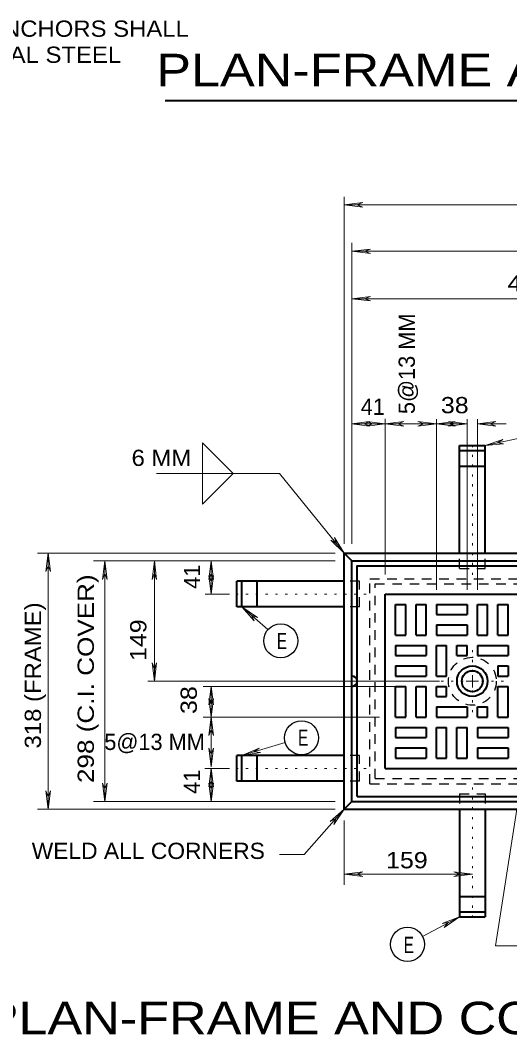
# Model space of a CAD drawing. Extents: x 312583 to 312854, y 144419 to 144597.
# Drawn here: x 312630.54 to 312653.44, y 144489.61 to 144537.06 of the extents above; entities that cross this region are included whole.
import ezdxf
from ezdxf.enums import TextEntityAlignment as Align

# ---------------------------------------------------------------- set-up
doc = ezdxf.new("R2010")
doc.units = 0
doc.header["$LTSCALE"] = 0.3
doc.linetypes.add('DOTTED', pattern=[1.5, 0.3, -1.2])
doc.linetypes.add('SHORT_DASHED', pattern=[2.7, 1.5, -1.2])
doc.layers.add('1', color=7, linetype='Continuous', lineweight=13)

msp = doc.modelspace()

# ---------------------------------------------------------------- linework, layer by layer
at = {"layer": '1', "lineweight": 40}
for p, q in [((312637.3201, 144533.3146), (312710.5195, 144533.3146)), ((312651.0931, 144517.1686), (312652.2891, 144517.1686)), ((312651.0931, 144512.1393), (312651.0931, 144517.1686)), ((312652.2891, 144512.1393), (312652.2891, 144517.1686)), ((312651.0931, 144516.931), (312652.2891, 144516.931)), ((312651.0931, 144516.2103), (312652.2891, 144516.2103)), ((312645.6958, 144500.1563), (312645.6958, 144512.1393)), ((312645.6958, 144512.1393), (312682.5955, 144512.1393)), ((312645.6958, 144512.1393), (312646.0561, 144511.779)), ((312646.0561, 144500.5166), (312646.0561, 144511.779)), ((312646.0561, 144511.779), (312682.2351, 144511.779)), ((312640.6665, 144509.6246), (312640.6665, 144510.8206)), ((312645.6958, 144510.8206), (312640.6665, 144510.8206)), ((312640.9041, 144509.6246), (312640.9041, 144510.8206)), ((312641.6248, 144509.6246), (312641.6248, 144510.8206)), ((312647.6125, 144502.073), (312647.6125, 144510.2226)), ((312647.6125, 144510.2226), (312680.6788, 144510.2226)), ((312645.6958, 144509.6246), (312640.6665, 144509.6246)), ((312648.0955, 144508.306), (312648.0955, 144509.7396)), ((312648.0955, 144509.7396), (312648.5708, 144509.7396)), ((312648.5708, 144508.306), (312648.5708, 144509.7396)), ((312649.0538, 144508.306), (312649.0538, 144509.7396)), ((312649.0538, 144509.7396), (312649.5291, 144509.7396)), ((312649.5291, 144508.306), (312649.5291, 144509.7396)), ((312650.0121, 144509.7396), (312651.4458, 144509.7396)), ((312650.0121, 144509.7396), (312650.0121, 144509.2643)), ((312651.4458, 144509.7396), (312651.4458, 144509.2643)), ((312651.9288, 144508.306), (312651.9288, 144509.7396)), ((312651.9288, 144509.7396), (312652.4041, 144509.7396)), ((312652.4041, 144508.306), (312652.4041, 144509.7396)), ((312652.8871, 144508.306), (312652.8871, 144509.7396)), ((312652.8871, 144509.7396), (312653.3625, 144509.7396)), ((312653.3625, 144508.306), (312653.3625, 144509.7396)), ((312650.0121, 144509.2643), (312651.4458, 144509.2643)), ((312650.0121, 144508.7813), (312651.4458, 144508.7813)), ((312650.0121, 144508.7813), (312650.0121, 144508.306)), ((312651.4458, 144508.7813), (312651.4458, 144508.306)), ((312648.0955, 144508.306), (312648.5708, 144508.306)), ((312649.0538, 144508.306), (312649.5291, 144508.306)), ((312650.0121, 144508.306), (312651.4458, 144508.306)), ((312651.9288, 144508.306), (312652.4041, 144508.306)), ((312652.8871, 144508.306), (312653.3625, 144508.306)), ((312648.0955, 144507.823), (312649.5291, 144507.823)), ((312648.0955, 144507.823), (312648.0955, 144507.3476)), ((312649.5291, 144507.823), (312649.5291, 144507.3476)), ((312650.0121, 144506.3893), (312650.0121, 144507.823)), ((312650.0121, 144507.823), (312650.4875, 144507.823)), ((312650.4875, 144506.3893), (312650.4875, 144507.823)), ((312650.9705, 144507.3476), (312650.9705, 144507.823)), ((312650.9705, 144507.823), (312651.4458, 144507.823)), ((312651.4458, 144507.3476), (312651.4458, 144507.823)), ((312651.9288, 144507.823), (312653.3625, 144507.823)), ((312651.9288, 144507.823), (312651.9288, 144507.3476)), ((312653.3625, 144507.823), (312653.3625, 144507.3476)), ((312648.0955, 144507.3476), (312649.5291, 144507.3476)), ((312650.9705, 144507.3476), (312651.4458, 144507.3476)), ((312651.9288, 144507.3476), (312653.3625, 144507.3476)), ((312648.0955, 144506.8646), (312649.5291, 144506.8646)), ((312648.0955, 144506.8646), (312648.0955, 144506.3893)), ((312649.5291, 144506.8646), (312649.5291, 144506.3893)), ((312652.8871, 144506.8646), (312653.3625, 144506.8646)), ((312652.8871, 144506.8646), (312652.8871, 144506.3893)), ((312653.3625, 144506.8646), (312653.3625, 144506.3893)), ((312648.0955, 144506.3893), (312649.5291, 144506.3893)), ((312650.0121, 144506.3893), (312650.4875, 144506.3893)), ((312652.8871, 144506.3893), (312653.3625, 144506.3893)), ((312648.0955, 144504.4726), (312648.0955, 144505.9063)), ((312648.0955, 144505.9063), (312648.5708, 144505.9063)), ((312648.5708, 144504.4726), (312648.5708, 144505.9063)), ((312649.0538, 144504.4726), (312649.0538, 144505.9063)), ((312649.0538, 144505.9063), (312649.5291, 144505.9063)), ((312649.5291, 144504.4726), (312649.5291, 144505.9063)), ((312650.0121, 144505.431), (312650.0121, 144505.9063)), ((312650.0121, 144505.9063), (312650.4875, 144505.9063)), ((312650.4875, 144505.431), (312650.4875, 144505.9063)), ((312652.8871, 144504.4726), (312652.8871, 144505.9063)), ((312652.8871, 144505.9063), (312653.3625, 144505.9063)), ((312653.3625, 144504.4726), (312653.3625, 144505.9063)), ((312650.0121, 144505.431), (312650.4875, 144505.431)), ((312650.0121, 144504.948), (312651.4458, 144504.948)), ((312650.0121, 144504.948), (312650.0121, 144504.4726)), ((312651.4458, 144504.948), (312651.4458, 144504.4726)), ((312651.9288, 144504.4726), (312651.9288, 144504.948)), ((312651.9288, 144504.948), (312652.4041, 144504.948)), ((312652.4041, 144504.4726), (312652.4041, 144504.948)), ((312648.0955, 144504.4726), (312648.5708, 144504.4726)), ((312649.0538, 144504.4726), (312649.5291, 144504.4726)), ((312650.0121, 144504.4726), (312651.4458, 144504.4726)), ((312651.9288, 144504.4726), (312652.4041, 144504.4726)), ((312652.8871, 144504.4726), (312653.3625, 144504.4726)), ((312648.0955, 144503.9896), (312649.5291, 144503.9896)), ((312648.0955, 144503.9896), (312648.0955, 144503.5143)), ((312649.5291, 144503.9896), (312649.5291, 144503.5143)), ((312650.0121, 144502.556), (312650.0121, 144503.9896)), ((312650.0121, 144503.9896), (312650.4875, 144503.9896)), ((312650.4875, 144502.556), (312650.4875, 144503.9896)), ((312650.9705, 144502.556), (312650.9705, 144503.9896)), ((312650.9705, 144503.9896), (312651.4458, 144503.9896)), ((312651.4458, 144502.556), (312651.4458, 144503.9896)), ((312651.9288, 144503.9896), (312653.3625, 144503.9896)), ((312651.9288, 144503.9896), (312651.9288, 144503.5143)), ((312653.3625, 144503.9896), (312653.3625, 144503.5143)), ((312648.0955, 144503.5143), (312649.5291, 144503.5143)), ((312651.9288, 144503.5143), (312653.3625, 144503.5143)), ((312648.0955, 144503.0313), (312649.5291, 144503.0313)), ((312648.0955, 144503.0313), (312648.0955, 144502.556)), ((312649.5291, 144503.0313), (312649.5291, 144502.556)), ((312651.9288, 144503.0313), (312653.3625, 144503.0313)), ((312651.9288, 144503.0313), (312651.9288, 144502.556)), ((312653.3625, 144503.0313), (312653.3625, 144502.556)), ((312640.6665, 144501.475), (312640.6665, 144502.671)), ((312645.6958, 144502.671), (312640.6665, 144502.671)), ((312640.9041, 144501.475), (312640.9041, 144502.671)), ((312641.6248, 144501.475), (312641.6248, 144502.671)), ((312648.0955, 144502.556), (312649.5291, 144502.556)), ((312650.0121, 144502.556), (312650.4875, 144502.556)), ((312650.9705, 144502.556), (312651.4458, 144502.556)), ((312651.9288, 144502.556), (312653.3625, 144502.556)), ((312647.6125, 144502.073), (312680.6788, 144502.073)), ((312645.6958, 144501.475), (312640.6665, 144501.475)), ((312645.6958, 144500.1563), (312646.0561, 144500.5166)), ((312646.0561, 144500.5166), (312682.2351, 144500.5166)), ((312646.3015, 144500.7543), (312681.9975, 144500.7543)), ((312645.6958, 144500.1563), (312682.5955, 144500.1563)), ((312651.0931, 144500.1563), (312651.0931, 144495.127)), ((312652.2891, 144500.1563), (312652.2891, 144495.127)), ((312651.0931, 144496.0853), (312652.2891, 144496.0853)), ((312651.0931, 144495.3646), (312652.2891, 144495.3646)), ((312651.0931, 144495.127), (312652.2891, 144495.127))]:
    msp.add_line(p, q, dxfattribs=at)
at = {"layer": '1'}
for p, q in [((312645.6958, 144512.5763), (312645.6958, 144528.8066)), ((312645.6958, 144528.4233), (312646.5621, 144528.5306)), ((312645.6958, 144528.4233), (312682.5955, 144528.4233)), ((312645.6958, 144528.4233), (312646.5621, 144528.316)), ((312646.5621, 144528.5306), (312646.2861, 144528.4233)), ((312646.5621, 144528.316), (312646.2861, 144528.4233)), ((312646.0561, 144512.5763), (312646.0561, 144526.6523)), ((312646.0561, 144526.2536), (312646.9225, 144526.361)), ((312646.0561, 144526.2536), (312682.2351, 144526.2536)), ((312646.0561, 144526.2536), (312646.9225, 144526.1463)), ((312646.9225, 144526.361), (312646.6465, 144526.2536)), ((312646.9225, 144526.1463), (312646.6465, 144526.2536)), ((312646.0561, 144524.038), (312646.9225, 144524.1453)), ((312646.9225, 144524.1453), (312646.6465, 144524.038)), ((312646.0561, 144524.038), (312664.1495, 144524.038)), ((312646.0561, 144524.038), (312646.9225, 144523.9306)), ((312646.9225, 144523.9306), (312646.6465, 144524.038)), ((312647.6125, 144511.135), (312647.6125, 144518.426)), ((312650.0121, 144510.4143), (312650.0121, 144518.4106)), ((312651.4458, 144510.4143), (312651.4458, 144518.4106)), ((312651.9288, 144510.4143), (312651.9288, 144518.4106)), ((312646.0331, 144518.1806), (312646.8995, 144518.288)), ((312646.0331, 144518.1806), (312646.8995, 144518.0733)), ((312646.8995, 144518.288), (312646.6235, 144518.1806)), ((312646.8995, 144518.0733), (312646.6235, 144518.1806)), ((312646.7461, 144518.288), (312647.0221, 144518.1806)), ((312647.6125, 144518.1806), (312646.7461, 144518.288)), ((312646.7461, 144518.0733), (312647.0221, 144518.1806)), ((312647.6125, 144518.1806), (312646.7461, 144518.0733)), ((312647.6125, 144518.1806), (312648.4788, 144518.288)), ((312647.6125, 144518.1806), (312648.4788, 144518.0733)), ((312648.4788, 144518.288), (312648.2028, 144518.1806)), ((312648.4788, 144518.0733), (312648.2028, 144518.1806)), ((312649.1458, 144518.288), (312649.4218, 144518.1806)), ((312650.0121, 144518.1806), (312649.1458, 144518.288)), ((312649.1458, 144518.0733), (312649.4218, 144518.1806)), ((312650.0121, 144518.1806), (312649.1458, 144518.0733)), ((312650.0121, 144518.1806), (312650.8785, 144518.288)), ((312650.0121, 144518.1806), (312650.8785, 144518.0733)), ((312650.5795, 144518.288), (312650.8555, 144518.1806)), ((312651.4458, 144518.1806), (312650.5795, 144518.288)), ((312650.5795, 144518.0733), (312650.8555, 144518.1806)), ((312651.4458, 144518.1806), (312650.5795, 144518.0733)), ((312650.8785, 144518.288), (312650.6025, 144518.1806)), ((312650.8785, 144518.0733), (312650.6025, 144518.1806)), ((312651.9288, 144518.1806), (312652.7951, 144518.288)), ((312651.9288, 144518.1806), (312653.2781, 144518.1806)), ((312651.9288, 144518.1806), (312652.7951, 144518.0733)), ((312655.8848, 144517.943), (312652.2891, 144517.1686)), ((312652.7951, 144518.288), (312652.5191, 144518.1806)), ((312652.7951, 144518.0733), (312652.5191, 144518.1806)), ((312652.2891, 144517.1686), (312653.1095, 144517.4523)), ((312653.1095, 144517.4523), (312652.8641, 144517.2913)), ((312652.2891, 144517.1686), (312653.1555, 144517.2453)), ((312653.1555, 144517.2453), (312652.8641, 144517.2913)), ((312636.9098, 144515.8576), (312642.6598, 144515.8576)), ((312642.6598, 144515.8576), (312645.6958, 144512.1393)), ((312645.0671, 144512.7373), (312645.3278, 144512.5916)), ((312645.6958, 144512.1393), (312645.0671, 144512.7373)), ((312645.2358, 144512.8753), (312645.3278, 144512.5916)), ((312645.6958, 144512.1393), (312645.2358, 144512.8753)), ((312645.2741, 144512.1393), (312631.3361, 144512.1393)), ((312631.8421, 144512.1393), (312631.7348, 144511.273)), ((312631.8421, 144500.1563), (312631.8421, 144512.1393)), ((312631.8421, 144512.1393), (312631.9495, 144511.273)), ((312645.2741, 144511.779), (312633.9581, 144511.779)), ((312634.4948, 144511.779), (312634.3875, 144510.9126)), ((312634.4948, 144500.5166), (312634.4948, 144511.779)), ((312634.4948, 144511.779), (312634.6021, 144510.9126)), ((312636.8101, 144511.779), (312636.7028, 144510.9126)), ((312636.8101, 144506.144), (312636.8101, 144511.779)), ((312636.8101, 144511.779), (312636.9175, 144510.9126)), ((312639.4628, 144511.779), (312639.3555, 144510.9126)), ((312639.4628, 144510.2226), (312639.4628, 144511.779)), ((312639.4628, 144511.779), (312639.5701, 144510.9126)), ((312631.7348, 144511.273), (312631.8421, 144511.549)), ((312631.9495, 144511.273), (312631.8421, 144511.549)), ((312634.3875, 144510.9126), (312634.4948, 144511.1886)), ((312634.6021, 144510.9126), (312634.4948, 144511.1886)), ((312636.7028, 144510.9126), (312636.8101, 144511.1886)), ((312636.9175, 144510.9126), (312636.8101, 144511.1886)), ((312639.3555, 144510.9126), (312639.4628, 144511.1886)), ((312639.3555, 144511.089), (312639.4628, 144510.813)), ((312639.4628, 144510.2226), (312639.3555, 144511.089)), ((312639.5701, 144510.9126), (312639.4628, 144511.1886)), ((312639.5701, 144511.089), (312639.4628, 144510.813)), ((312639.4628, 144510.2226), (312639.5701, 144511.089)), ((312640.3215, 144510.2226), (312639.1945, 144510.2226)), ((312642.1231, 144508.559), (312640.9041, 144509.6246)), ((312640.9041, 144509.6246), (312641.4868, 144508.973)), ((312640.9041, 144509.6246), (312641.6325, 144509.134)), ((312641.4868, 144508.973), (312641.3488, 144509.2336)), ((312641.6325, 144509.134), (312641.3488, 144509.2336)), ((312636.7028, 144507.0103), (312636.8101, 144506.7343)), ((312636.8101, 144506.144), (312636.7028, 144507.0103)), ((312636.9175, 144507.0103), (312636.8101, 144506.7343)), ((312636.8101, 144506.144), (312636.9175, 144507.0103)), ((312650.1578, 144506.144), (312636.5111, 144506.144)), ((312651.6911, 144506.144), (312651.3998, 144506.144)), ((312651.6911, 144506.144), (312651.6911, 144506.4353)), ((312651.6911, 144506.144), (312651.6911, 144505.8603)), ((312651.6911, 144506.144), (312651.9748, 144506.144)), ((312648.0955, 144505.9063), (312639.0948, 144505.9063)), ((312639.4628, 144505.9063), (312639.3555, 144505.04)), ((312639.4628, 144505.9063), (312639.5701, 144505.04)), ((312639.3555, 144505.339), (312639.4628, 144505.063)), ((312639.4628, 144504.4726), (312639.3555, 144505.339)), ((312639.3555, 144505.04), (312639.4628, 144505.316)), ((312639.5701, 144505.339), (312639.4628, 144505.063)), ((312639.4628, 144504.4726), (312639.5701, 144505.339)), ((312639.5701, 144505.04), (312639.4628, 144505.316)), ((312647.3441, 144504.4726), (312639.0948, 144504.4726)), ((312639.4628, 144504.4726), (312639.3555, 144503.6063)), ((312639.4628, 144504.4726), (312639.5701, 144503.6063)), ((312639.3555, 144503.6063), (312639.4628, 144503.8823)), ((312639.5701, 144503.6063), (312639.4628, 144503.8823)), ((312642.9358, 144503.2766), (312640.9041, 144502.671)), ((312639.3555, 144503.016), (312639.4628, 144502.74)), ((312639.4628, 144502.1496), (312639.3555, 144503.016)), ((312639.5701, 144503.016), (312639.4628, 144502.74)), ((312639.4628, 144502.1496), (312639.5701, 144503.016)), ((312640.9041, 144502.671), (312641.7091, 144503.0236)), ((312640.9041, 144502.671), (312641.7705, 144502.8166)), ((312641.7091, 144503.0236), (312641.4715, 144502.8396)), ((312641.7705, 144502.8166), (312641.4715, 144502.8396)), ((312640.3215, 144502.073), (312639.1791, 144502.073)), ((312639.4628, 144502.073), (312639.3555, 144501.2066)), ((312639.4628, 144500.5166), (312639.4628, 144502.073)), ((312639.4628, 144502.073), (312639.5701, 144501.2066)), ((312634.3875, 144501.383), (312634.4948, 144501.107)), ((312634.4948, 144500.5166), (312634.3875, 144501.383)), ((312634.6021, 144501.383), (312634.4948, 144501.107)), ((312634.4948, 144500.5166), (312634.6021, 144501.383)), ((312639.3555, 144501.2066), (312639.4628, 144501.4826)), ((312639.3555, 144501.383), (312639.4628, 144501.107)), ((312639.4628, 144500.5166), (312639.3555, 144501.383)), ((312639.5701, 144501.2066), (312639.4628, 144501.4826)), ((312639.5701, 144501.383), (312639.4628, 144501.107)), ((312639.4628, 144500.5166), (312639.5701, 144501.383)), ((312631.7348, 144501.0226), (312631.8421, 144500.7466)), ((312631.8421, 144500.1563), (312631.7348, 144501.0226)), ((312631.9495, 144501.0226), (312631.8421, 144500.7466)), ((312631.8421, 144500.1563), (312631.9495, 144501.0226)), ((312645.2741, 144500.5166), (312633.9581, 144500.5166)), ((312645.2741, 144500.1563), (312631.3361, 144500.1563)), ((312645.6958, 144500.1563), (312645.0441, 144499.5813)), ((312645.6958, 144500.1563), (312645.2051, 144499.4433)), ((312645.0441, 144499.5813), (312645.3048, 144499.7193)), ((312645.2051, 144499.4433), (312645.3048, 144499.7193)), ((312645.6958, 144499.635), (312645.6958, 144496.622)), ((312645.6958, 144497.1203), (312646.5621, 144497.2276)), ((312645.6958, 144497.1203), (312651.6911, 144497.1203)), ((312645.6958, 144497.1203), (312646.5621, 144497.013)), ((312646.5621, 144497.2276), (312646.2861, 144497.1203)), ((312646.5621, 144497.013), (312646.2861, 144497.1203)), ((312650.8248, 144497.2276), (312651.1008, 144497.1203)), ((312651.6911, 144497.1203), (312650.8248, 144497.2276)), ((312650.8248, 144497.013), (312651.1008, 144497.1203)), ((312651.6911, 144497.1203), (312650.8248, 144497.013)), ((312649.3605, 144494.2146), (312651.0931, 144495.127)), ((312651.0931, 144495.127), (312650.2728, 144494.8203)), ((312650.2728, 144494.8203), (312650.5641, 144494.8586)), ((312651.0931, 144495.127), (312650.3725, 144494.6363)), ((312650.3725, 144494.6363), (312650.5641, 144494.8586))]:
    msp.add_line(p, q, dxfattribs=at)
at = {"layer": '1', "linetype": 'DOTTED'}
for p, q in [((312651.6911, 144511.1196), (312651.6911, 144517.5213)), ((312646.7155, 144510.2226), (312640.3215, 144510.2226)), ((312651.6911, 144506.581), (312651.6911, 144507.6926)), ((312651.2541, 144506.144), (312650.1578, 144506.144)), ((312652.1205, 144506.144), (312653.2551, 144506.144)), ((312651.6911, 144505.7146), (312651.6911, 144504.557)), ((312646.7155, 144502.073), (312640.3215, 144502.073)), ((312651.6911, 144501.176), (312651.6911, 144494.7743))]:
    msp.add_line(p, q, dxfattribs=at)
at = {"layer": '1', "linetype": 'SHORT_DASHED', "lineweight": 25}
for p, q in [((312651.0931, 144511.4186), (312651.0931, 144512.1393)), ((312652.2891, 144511.4186), (312652.2891, 144512.1393)), ((312651.0931, 144511.4186), (312652.2891, 144511.4186)), ((312646.4165, 144510.8206), (312645.6958, 144510.8206)), ((312646.4165, 144509.6246), (312646.4165, 144510.8206)), ((312646.8995, 144510.9356), (312681.3995, 144510.9356)), ((312646.8995, 144501.3523), (312646.8995, 144510.9356)), ((312646.4165, 144509.6246), (312645.6958, 144509.6246)), ((312646.4165, 144502.671), (312645.6958, 144502.671)), ((312646.4165, 144501.475), (312646.4165, 144502.671)), ((312646.4165, 144501.475), (312645.6958, 144501.475)), ((312646.8995, 144501.3523), (312681.3995, 144501.3523)), ((312647.1371, 144501.5976), (312681.1541, 144501.5976)), ((312651.0931, 144500.877), (312652.2891, 144500.877)), ((312651.0931, 144500.877), (312651.0931, 144500.1563)), ((312652.2891, 144500.877), (312652.2891, 144500.1563))]:
    msp.add_line(p, q, dxfattribs=at)
at = {"layer": '1'}
for points in [[(312646.0331, 144518.1806), (312647.6125, 144518.1806), (312650.0121, 144518.1806), (312651.4458, 144518.1806)], [(312640.5055, 144515.8576), (312639.0641, 144517.299), (312639.0641, 144515.8576)], [(312640.5055, 144515.8576), (312639.0641, 144514.424), (312639.0641, 144515.8576)], [(312639.4628, 144502.1496), (312639.4628, 144504.4726), (312639.4628, 144505.9063)], [(312642.6598, 144498.048), (312643.8175, 144498.048), (312645.6958, 144500.1563)], [(312654.1291, 144493.7776), (312652.7798, 144493.7776), (312653.7765, 144500.1563)]]:
    msp.add_lwpolyline(points, dxfattribs=at)
at = {"layer": '1', "lineweight": 40}
msp.add_lwpolyline([(312646.3015, 144500.7543), (312646.3015, 144511.5413), (312681.9975, 144511.5413)], dxfattribs=at)
at = {"layer": '1', "linetype": 'SHORT_DASHED', "lineweight": 25}
msp.add_lwpolyline([(312647.1371, 144501.5976), (312647.1371, 144510.698), (312681.1541, 144510.698)], dxfattribs=at)
at = {"layer": '1', "lineweight": 25}
for centre in [(312642.7231, 144508.0357), (312643.6967, 144503.5018), (312648.6551, 144493.8409)]:
    msp.add_circle(centre, 0.7964, dxfattribs=at)
at = {"layer": '1', "linetype": 'SHORT_DASHED', "lineweight": 25}
msp.add_circle((312651.6883, 144506.1478), 1.1201, dxfattribs=at)
at = {"layer": '1', "lineweight": 40}
for radius in [0.7155, 0.4899]:
    msp.add_circle((312651.6883, 144506.1478), radius, dxfattribs=at)
msp.add_arc((312646.058, 144506.1478), 0.2396, 270, 90, dxfattribs=at)

# ---------------------------------------------------------------- texts
at = {"layer": '1'}
for s, width, p in [('FRAME AND ANCHORS SHALL', 1.1, (312622.0883, 144536.2883)), ('BE STRUCTURAL STEEL', 1.1, (312622.0883, 144535.0683)), ('479 ', 1.2, (312653.3299, 144524.3763)), ('38 ', 1.15, (312650.218, 144518.6802)), ('6 MM', 1.1, (312635.7429, 144516.2151)), ('E', 0.7, (312642.5428, 144507.65)), ('E', 0.7, (312643.5341, 144503.1291)), ('WELD ALL CORNERS', 1.05, (312631.071, 144497.8343)), ('159 ', 1.15, (312647.6516, 144497.3973)), ('E', 0.7, (312648.4768, 144493.4336))]:
    msp.add_text(s, height=0.76, dxfattribs=dict(at, width=width)).set_placement(p)
at = {"layer": '1', "width": 1.2}
for s, p in [('PLAN-FRAME AND COVER FOR 450 BY 900 MM JUNCTION BOX', (312673.7634, 144533.9741)), ('PLAN-FRAME AND COVER FOR 250 BY 900 MM JUNCTION BOX', (312665.6882, 144489.6359))]:
    msp.add_text(s, height=1.52, dxfattribs=at).set_placement(p, align=Align.CENTER)
at = {"layer": '1'}
for s, p in [('5@13 MM', (312648.999, 144518.6414)), ('41 ', (312638.9529, 144510.4684)), ('41 ', (312638.9477, 144500.8789))]:
    msp.add_text(s, height=0.76, rotation=90, dxfattribs=at).set_placement(p)
for s, p in [('41 ', (312646.4667, 144518.6061)), ('5@13 MM', (312634.4679, 144502.9307))]:
    msp.add_text(s, height=0.76, dxfattribs=at).set_placement(p)
for s, width, p in [('298 (C.I. COVER)', 1.2, (312633.9799, 144501.3858)), ('318 (FRAME)', 1.1, (312631.5043, 144503.0014)), ('149 ', 1.15, (312636.4369, 144507.0906)), ('38 ', 1.15, (312638.7981, 144504.6145))]:
    msp.add_text(s, height=0.76, rotation=90, dxfattribs=dict(at, width=width)).set_placement(p)

doc.saveas('drawing.dxf')
